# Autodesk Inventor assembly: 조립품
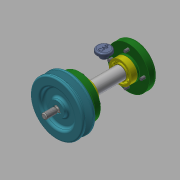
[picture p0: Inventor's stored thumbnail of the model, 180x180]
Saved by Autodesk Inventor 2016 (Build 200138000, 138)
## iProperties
Created: 2018-12
Part Number: 조립품
Material: 일반
Document SubType Name: Assembly
Designer: 605-08
Author: 605-08
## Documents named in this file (11)
- C:\Users\605-08\Desktop\481207V1006\조립품.iam
- C:\Users\605-08\Desktop\481207V1006\본체.ipt
- C:\Users\605-08\Desktop\481207V1006\베어링 15 x 32 x 9.ipt
- C:\Users\605-08\Desktop\481207V1006\축.ipt
- C:\Users\605-08\Desktop\481207V1006\앞커버.ipt
- C:\Users\605-08\Desktop\481207V1006\뒤커버.ipt
- C:\Users\605-08\Desktop\481207V1006\오일 실 15 25 7.ipt
- C:\Users\605-08\Desktop\481207V1006\키 3 x 3 x 12.ipt
- C:\Users\605-08\Desktop\481207V1006\고무캡.ipt
- C:\Users\605-08\Desktop\481207V1006\볼트 M4 x 12.ipt
- C:\Users\605-08\Desktop\481207V1006\V벨트풀리.ipt
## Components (2 placed, 2 different names)
1. 고무캡:1
2. V벨트풀리:1
